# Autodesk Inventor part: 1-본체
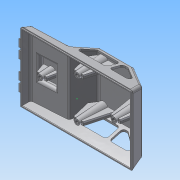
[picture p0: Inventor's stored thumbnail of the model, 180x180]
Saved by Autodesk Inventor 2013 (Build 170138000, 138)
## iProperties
Created: 2015-05
Part Number: 1-본체
Material: ABS 플라스틱
Document SubType Name: Modeling
Designer: Administrator
Mass: 36.1241 g
Surface Area: 335.97 cm^2
Volume: 34.0793 cm^3
Density: 1.06 g/cm^3
Author: Administrator
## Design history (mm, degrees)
sketch "스케치1"
  geometry: L1 (-61, 0)-(61, 0); L2 (-61, 0)-(-58.588, 9); L3 (-58.588, 9)-(-19, 11.075); L4 (-19, 11.075)-(-6.549, 31); L5 (-6.549, 31)-(31, 31); L6 (31, 31)-(57.412, 13.392); L7 (57.412, 13.392)-(61, 0); 3 further points
  constraints: 14 end point, 1 coincident, 1 horizontal, 1 midpoint, 1 parallel, 1 point on line, 1 vertical alignment
  dimensions: "d4" = 122 distance of L1.start L1.end; "d6" = 105 deg angle of L1 L2; "d10" = 31 vertical distance of L1.end L5.end; "d12" = 9 distance from line of L1 L2.end; "d13" = 125 deg angle of L4 L3; "d14" = 105 deg angle of L1 L7; "d16" = 3 deg angle of L1 L3; "d39" = 30 horizontal distance of L1.end L5.end; "d46" = 20 vertical distance of point (61, 11) L5.end; "d55" = 42 horizontal distance of L3.end L1.start
extrude "돌출1" new body sketch "스케치1" stored distance "d17" = 76; taper "d18" = 0 deg
sketch "스케치5"
  geometry: L1 (0, 76)-(0, 0) reference; L2 (8.121, 51)-(28.121, 51); L3 (28.121, 51)-(28.121, 25); L4 (28.121, 25)-(8.121, 25); L5 (8.121, 25)-(8.121, 51); L6 (-2.879, 0)-(-2.879, 76) reference; 3 further points
  constraints: 8 end point, 2 midpoint, 2 parallel, 1 horizontal, 1 horizontal alignment, 1 perpendicular
  dimensions: "d57" = 26 distance of L2.end L3.end; "d59" = 20 distance of L2.start L2.end; "d97" = 11 distance between parallel lines of L5 L6
extrude "돌출3" join sketch "스케치5" distance "d61" = 5; taper "d62" = 0 deg
sketch "스케치2"
  geometry: L1 (0, 38)-(0, -38) reference; L2 (0, 38)-(31, 29.694); L3 (31, -29.694)-(0, -38); L4 (31, -38)-(31, 38) reference; L5 (11.075, -38)-(31, -38) reference; L6 (0, -38)-(9, -38) reference; L7 (9, -38)-(11.075, -38) reference; L8 (31, 38)-(11.075, 38) reference; L9 (9, 38)-(0, 38) reference; L10 (11.075, 38)-(9, 38) reference; 1 further point
  constraints: 4 end point, 2 point on line
  dimensions: "d19" = 105 deg angle of L1 L3; "d20" = 105 deg angle of L1 L2
extrude "돌출2" cut sketch "스케치2" stored distance "d23" = 76; taper "d24" = 0 deg
feature "쉘1" dims "d56" = 2
sketch "스케치6"
  geometry: L1 (119.929, -2.071)-(119.929, -73.929) reference; L2 (119.929, -73.929)-(2.071, -73.929) reference; L3 (2.071, -73.929)-(2.071, -2.071) reference; L4 (2.071, -2.071)-(119.929, -2.071) reference; L5 (122, -76)-(122, 0) reference; L6 (0, 0)-(122, 0) reference; L7 (0, 0)-(0, -76) reference; L8 (122, -76)-(0, -76) reference; L9 (121, -1)-(121, -75); L10 (121, -75)-(1, -75); L11 (1, -75)-(1, -1); L12 (1, -1)-(121, -1); 1 further point
  constraints: 8 end point, 3 other
  dimensions: "d63" = 1 distance between parallel lines of L6 L12
extrude "돌출4" join sketch "스케치6" distance "d64" = 1; taper "d65" = 0 deg
sketch "스케치7"
  geometry: L1 (-19, 11.075)-(-6.549, 31) reference; L2 (-6.549, 31)-(31, 31) reference; L3 (31, 31)-(57.412, 13.392) reference; L4 (-13.151, 11)-(-3.778, 26); L5 (-3.778, 26)-(20.849, 26); L6 (20.849, 26)-(20.849, 11); L7 (20.849, 11)-(-13.151, 11); L8 (23.986, 26)-(23.986, 11); L9 (23.986, 11)-(51.986, 11); L10 (51.986, 11)-(29.486, 26); L11 (29.486, 26)-(23.986, 26); 1 further point
  constraints: 16 end point, 4 parallel, 4 perpendicular
  dimensions: "d66" = 34 distance of L6.end L4.start; "d68" = 5 distance between parallel lines of L2 L5; "d69" = 5 distance between parallel lines of L1 L4; "d70" = 15 vertical distance of L4.start L4.end; "d71" = 28 distance of L8.end L9.end; "d72" = 5 distance between parallel lines of L3 L10; "d73" = 5 distance from line of L2 L10.end; "d74" = 15 distance of L8.start L8.end
extrude "돌출5" cut sketch "스케치7" stored distance "d75" = 1; taper "d76" = 0 deg
node "작업 평면1"
sketch "스케치9"
  geometry: A1 r 4 centre (0, -21) between (0, -17) and (0, -25); A2 r 4 centre (0, -10) between (0, -6) and (0, -14); A3 r 4 centre (0, 10) between (0, 14) and (0, 6); A4 r 4 centre (0, 21) between (0, 25) and (0, 17); 3 further points
  constraints: 8 point on circle, 4 centre point, 3 equal radius, 13 other
  dimensions: "d78" = 11 distance of A2.centre A1.centre; "d80" = 4 radius of A1; "d81" = 20 distance of A3.centre A2.centre; "d82" = 10 distance of point (0, 0) A2.centre; "d83" = 11 distance of A4.centre A3.centre
extrude "돌출6" join sketch "스케치9" stored distance "d84" = 1; taper "d85" = 0 deg
sketch "스케치10"
  geometry: L1 (122, -76)-(122, 0) reference; C1 r 3 at (21, -38); C2 r 3 at (101, -38); C3 r 3 at (61, -60); C4 r 3 at (61, -16); 1 further point
  constraints: 4 centre point, 2 horizontal alignment, 2 vertical alignment
  dimensions: "d86" = 6 diameter of C1; "d88" = 6 diameter of C2; "d89" = 40 distance of point (61, -38) C1.centre; "d90" = 21 distance from line of L1 C2.centre; "d91" = 6 diameter of C3; "d92" = 22 distance of point (61, -38) C3.centre; "d93" = 6 diameter of C4; "d94" = 22 distance of point (61, -38) C4.centre
extrude "돌출7" join sketch "스케치10" stored distance "d95" = 1; taper "d96" = 4 deg
sketch "스케치14"
  geometry: L1 (23.986, 26)-(29.486, 26) reference; L2 (29.486, 26)-(51.986, 11) reference; L3 (51.986, 11)-(23.986, 11) reference; L4 (23.986, 11)-(23.986, 26) reference; L5 (-3.778, 26)-(20.849, 26) reference; L6 (20.849, 26)-(20.849, 11) reference; L7 (20.849, 11)-(-13.151, 11) reference; L8 (-13.151, 11)-(-3.778, 26) reference; L9 (-19, 11.075)-(-6.549, 31) reference; L10 (-58.588, 9)-(-19, 11.075) reference; L11 (-61, 0)-(-58.588, 9) reference; L12 (-61, 0)-(61, 0) reference; L13 (57.412, 13.392)-(61, 0) reference; L14 (31, 31)-(57.412, 13.392) reference; L15 (-6.549, 31)-(31, 31) reference; L16 (37, 0)-(35.196, 25.799) reference; L17 (43, 0)-(44.376, 19.679) reference; L18 (30.394, 29)-(55.675, 12.146) reference; L19 (35, 2)-(36.86, 2); L20 (43.14, 2)-(45, 2); L21 (30.394, 29)-(35, 2); L22 (45, 2)-(47.803, 17.394); 1 further point
  constraints: 8 end point, 3 point on line, 2 collinear, 2 parallel
  dimensions: "d118" = 10 distance of L19.start L20.end; "d121" = 2 distance between parallel lines of L12 L20; "d124" = 20 deg angle of L21 L22
extrude "돌출8" join sketch "스케치14" stored distance "d125" = 4; taper "d126" = 5 deg
sketch "스케치15"
  geometry: 1 further point
fillet "모깎기1" dims "d127" = 3
sketch "스케치16"
  geometry: L1 (-30.663, 13.468)-(-50.636, 12.421) reference; L2 (-48.534, 10.528)-(-48.639, 12.526) reference; L3 (-32.556, 11.366)-(-32.661, 13.363) reference; L4 (-43, 0)-(-43.893, 12.774) reference; L5 (-37, 0)-(-36.078, 13.184) reference; L6 (-48.639, 12.526)-(-45, 2); L7 (-35, 2)-(-32.661, 13.363); L8 (-61, 0)-(61, 0) reference; L9 (-45, 2)-(-43.14, 2); L10 (-36.86, 2)-(-35, 2); 1 further point
  constraints: 8 end point, 3 collinear, 2 point on line, 1 parallel
  dimensions: "d129" = 2 distance from line of L8 L7.start; "d130" = 10 distance of L7.start L6.end
extrude "돌출9" join sketch "스케치16" stored distance "d131" = 4; taper "d132" = 5 deg
node "작업 평면2"
sketch "스케치17"
  geometry: L1 (-5.441, 29)-(30.394, 29) reference; L2 (-17.856, 9.132)-(-5.441, 29) reference; L3 (-3, 0)-(-5.028, 29) reference; L4 (3, 0)-(5.028, 29) reference; L5 (12.477, 29)-(5, 2); L6 (-61, 0)-(61, 0) reference; L7 (5, 2)-(3.14, 2); L8 (-3.14, 2)-(-5, 2); L9 (-5, 2)-(-9.815, 22); 1 further point
  constraints: 8 end point, 3 collinear, 3 point on line, 1 midpoint, 1 parallel
  dimensions: "d134" = 2 distance between parallel lines of L6 L7; "d138" = 10 distance of L5.end L8.end; "d141" = 76.4642 deg angle of L1 L9
extrude "돌출10" join sketch "스케치17" stored distance "d142" = 4; taper "d143" = 5 deg
sketch "스케치12"
  geometry: C1 r 3 at (0, 0) reference; C2 r 3 at (40, 22) reference; C3 r 3 at (80, 0) reference; C4 r 3 at (40, -22) reference; 5 further points
  constraints: 4 coincident
hole "구멍1" sketch "스케치12" at (0, 0), (40, 22), (40, -22), (80, 0) diameter "d106" = 3.242; stored, may be unused: countersink angle "d110" = 90 deg, drill point angle "d112" = 118 deg; dims "d107" = 9, "d108" = 4, "d109" = 2, "d111" = 11
sketch "스케치13"
  geometry: L1 (67.549, 67.694)-(67.549, -8.306) reference; 3 further points
  constraints: 1 horizontal alignment, 1 midpoint, 1 other
  dimensions: "d113" = 50 distance from line of L1 point (17.549, 29.694)
feature "엠보싱1" sketch "스케치13" dims "d114" = 0.5, "d115" = 0
fillet "모깎기2" dims "d144" = 3
fillet "모깎기3" dims "d145" = 3
fillet "모깎기4" dims "d146" = 3
fillet "모깎기5" dims "d147" = 3
fillet "모깎기6" dims "d148" = 3
fillet "모깎기7" dims "d149" = 3
fillet "모깎기8" dims "d150" = 3
node "솔리드1"
mirror "대칭1"
node "투영된 루프2"
other parameters: "d77" = -63, "d120" = 2, "d133" = 22
